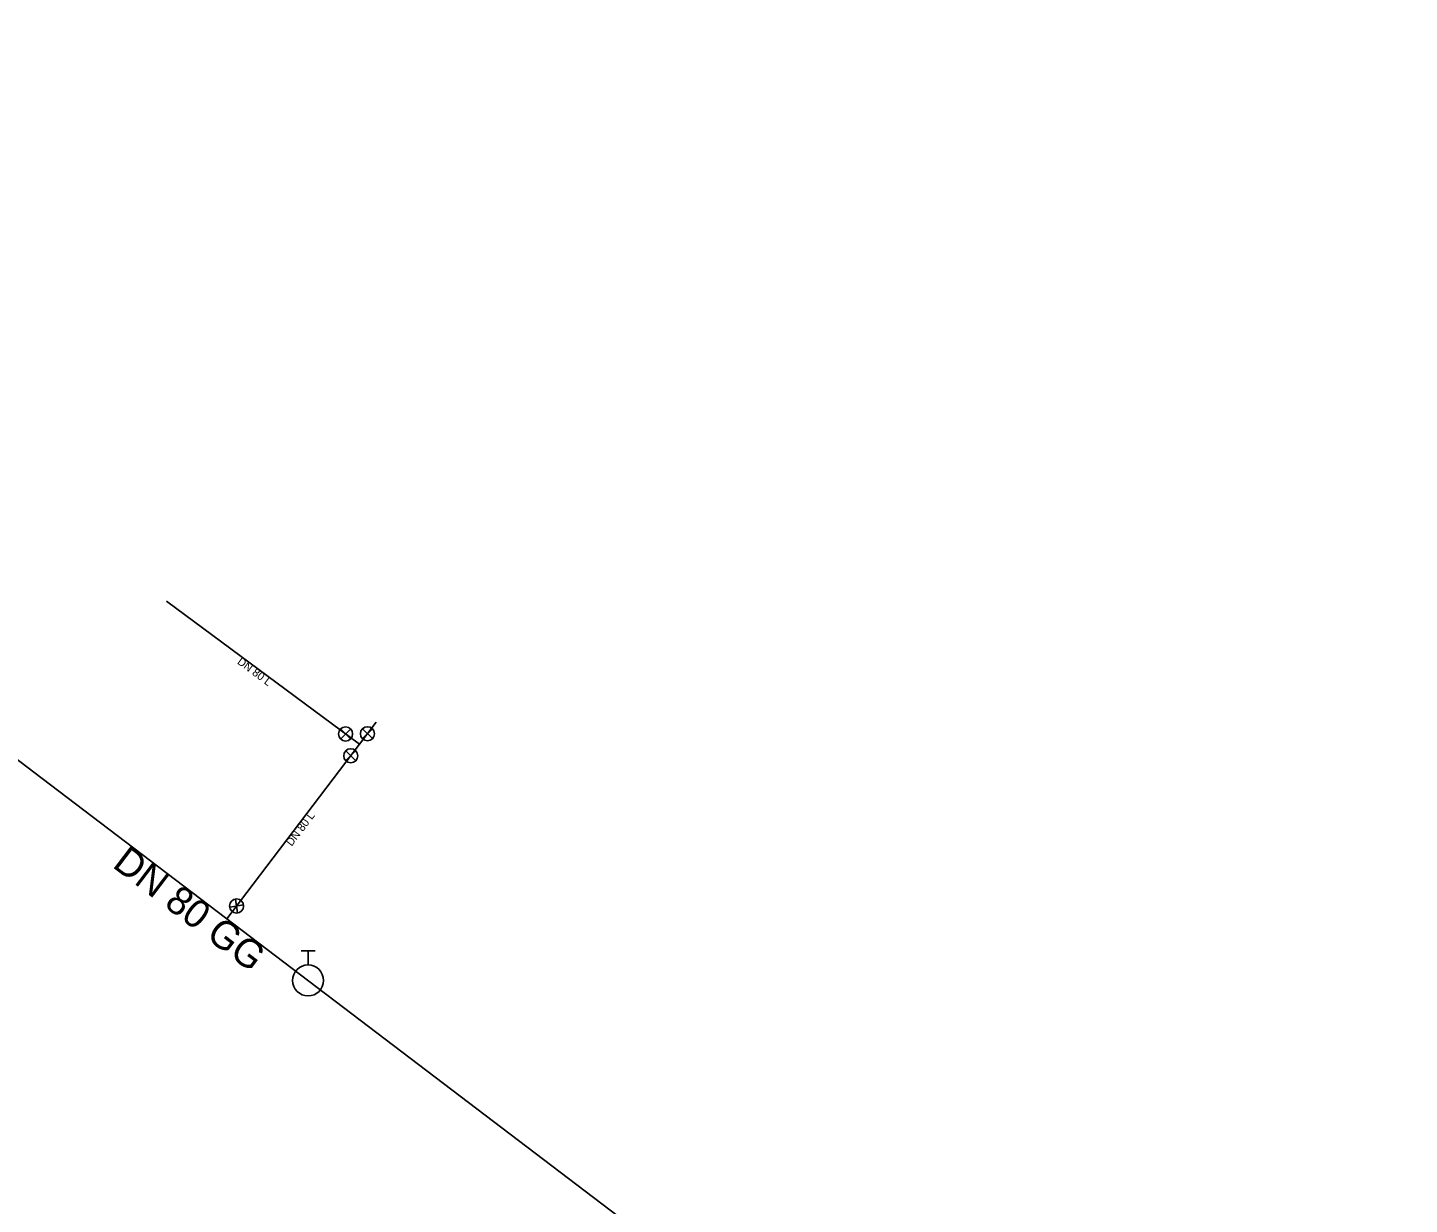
# Model space of a CAD drawing. Extents: x -492321 to -492053, y -1126159 to -1125902.
# Drawn here: x -492170.4 to -492091.8, y -1125969.2 to -1125902.3 of the extents above; entities that cross this region are included whole.
import ezdxf

# ---------------------------------------------------------------- set-up
doc = ezdxf.new("R2010")
doc.units = 0
for name, color, linetype in [('_pripojka_prevzato_z_dokumentace_', 7, 'Continuous'), ('_voda_smvak_prevzato_z_dokumentace_', 7, 'Continuous'), ('Default', 7, 'Continuous'), ('MoLevel 28', 7, 'Continuous'), ('MoLevel 46', 7, 'Continuous'), ('MoLevel 53', 7, 'Continuous'), ('MoLevel 55', 7, 'Continuous')]:
    doc.layers.add(name, color=color, linetype=linetype)

# ---------------------------------------------------------------- blocks, each defined once
blk = doc.blocks.new('_uzaver_pripojka_')
at = {"layer": 'Default'}
for p, q in [((-0.000035, -0.000035), (0.000035, 0.000035)), ((0.000035, -0.000035), (-0.000035, 0.000035))]:
    blk.add_line(p, q, dxfattribs=at)
for radius in [0.00005, 0.0000025]:
    blk.add_circle((0, 0), radius, dxfattribs=at)
blk = doc.blocks.new('_hydrant_voda_')
at = {"layer": 'Default'}
for p, q in [((-0.0000225, 0.000095), (0.0000225, 0.000095)), ((0, 0.000095), (0, 0.00005))]:
    blk.add_line(p, q, dxfattribs=at)
blk.add_circle((0, 0), 0.00005, dxfattribs=at)

msp = doc.modelspace()

# ---------------------------------------------------------------- linework, layer by layer
at = {"layer": '_pripojka_prevzato_z_dokumentace_'}
for p, q in [((-492151.554, -1125943.028), (-492162.53, -1125934.895)), ((-492150.607, -1125941.781), (-492151.554, -1125943.028)), ((-492151.554, -1125943.028), (-492159.094, -1125952.953))]:
    msp.add_line(p, q, dxfattribs=at)
at = {"layer": '_voda_smvak_prevzato_z_dokumentace_'}
for points in [[(-492225.3, -1125902.29), (-492220.567, -1125906.046), (-492209.52, -1125914.07), (-492209.4, -1125914.36), (-492198.6, -1125922.92), (-492193.91, -1125926.58), (-492186.03, -1125932.73), (-492171.197, -1125943.758), (-492170.066, -1125944.617)], [(-492170.066, -1125944.617), (-492136.347, -1125970.233), (-492094.876, -1126002.677), (-492091.849, -1126005.375)]]:
    msp.add_lwpolyline(points, dxfattribs=at)

# ---------------------------------------------------------------- block references
at = {"layer": 'MoLevel 28', "xscale": 17636.68430335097, "yscale": 17636.68430335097}
msp.add_blockref('_hydrant_voda_', (-492154.478, -1125956.459), dxfattribs=at)
at = {"layer": 'MoLevel 53', "yscale": 7999.999999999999}
for p, xscale, rotation in [((-492152.341, -1125942.445), 7999.999999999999, 90), ((-492151.101, -1125942.431), 7999.999999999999, 90), ((-492152.051, -1125943.683), 7999.999999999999, 90), ((-492158.54, -1125952.226), 8000, 53.4716222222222)]:
    msp.add_blockref('_uzaver_pripojka_', p, dxfattribs=dict(at, xscale=xscale, rotation=rotation))

# ---------------------------------------------------------------- texts
at = {"layer": 'MoLevel 46'}
msp.add_text('DN 80 GG', height=1.6049, rotation=322.77664, dxfattribs=at).set_placement((-492165.665, -1125949.976))
at = {"layer": 'MoLevel 55'}
for rotation, p in [(323.46229, (-492158.54, -1125938.418)), (52.77726, (-492155.412, -1125948.859))]:
    msp.add_text('DN 80 L', height=0.455, rotation=rotation, dxfattribs=at).set_placement(p)

doc.saveas('drawing.dxf')
